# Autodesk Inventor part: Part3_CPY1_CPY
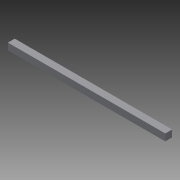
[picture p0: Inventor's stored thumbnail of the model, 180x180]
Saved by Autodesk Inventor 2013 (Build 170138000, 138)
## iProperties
Created: 2013-06
Part Number: Part3_CPY1_CPY
Material: Generic
Document SubType Name: Modeling
Designer: jpfenske
Mass: 1272.05 g
Surface Area: 1364.51 cm^2
Volume: 1272.05 cm^3
Density: 1 g/cm^3
Author: jpfenske
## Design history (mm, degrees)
sketch "Sketch1"
  geometry: L1 (-414.892, 325.462)-(461.408, 325.462); L2 (461.408, 325.462)-(461.408, 287.362); L3 (461.408, 287.362)-(-414.892, 287.362); L4 (-414.892, 287.362)-(-414.892, 325.462); 1 further point
  constraints: 8 end point, 2 parallel, 1 horizontal, 1 perpendicular
  dimensions: "d0" = 876.3 distance of L1.start L1.end; "d1" = 38.1 distance of L1.end L2.end
extrude "Extrusion1" new body sketch "Sketch1" distance "d2" = 38.1; taper "d3" = 0 deg
body "Solid1"
